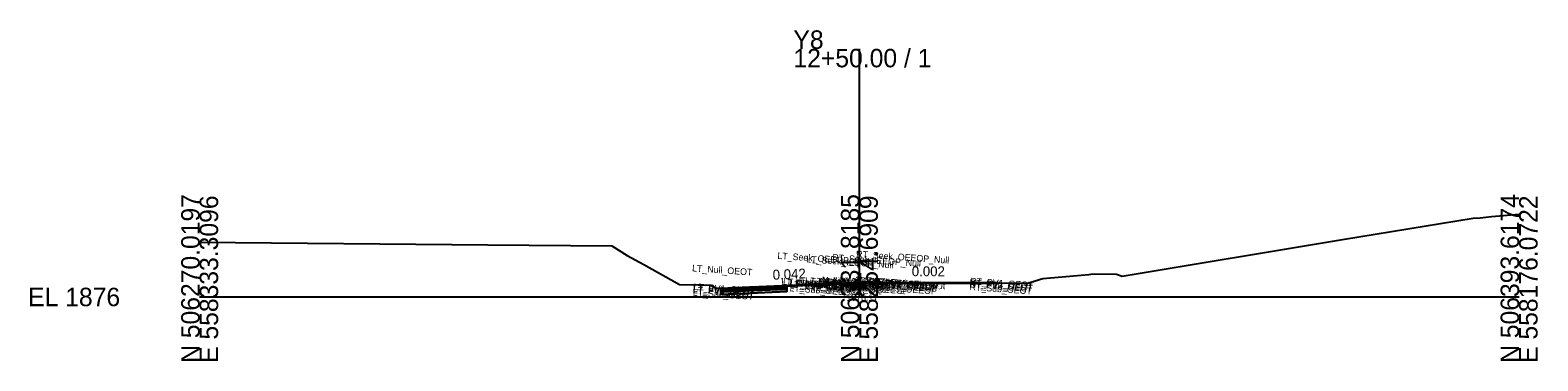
# Model space of a CAD drawing. Extents: x -26 to 203, y -10 to 8070.
# Drawn here: x -25.7 to 202.8, y 2490.3 to 2540.5 of the extents above; entities that cross this region are included whole.
import ezdxf

# ---------------------------------------------------------------- set-up
doc = ezdxf.new("R2010")
doc.units = 0
for name, color, linetype in [('Default', 7, 'Continuous'), ('Exist Cross Section Cell', 7, 'Continuous'), ('Exist XS Center Line Elevation Label', 7, 'Continuous'), ('Exist XS Ground Line', 7, 'Continuous'), ('Prop CMT Pvmt Course 1', 7, 'Continuous'), ('Prop CMT Pvmt Course 2', 7, 'Continuous'), ('Prop CMT Pvmt Course 3', 7, 'Continuous'), ('Prop CMT Pvmt Surface', 7, 'Continuous'), ('Prop CMT Subgrade Earthwork', 7, 'Continuous'), ('Prop XS Earthwork Shape', 7, 'Continuous'), ('Prop XS SE Text', 7, 'Continuous'), ('Typical Text Grade Point CELL', 7, 'Continuous')]:
    doc.layers.add(name, color=color, linetype=linetype)

msp = doc.modelspace()

# ---------------------------------------------------------------- linework, layer by layer
at = {"layer": 'Exist Cross Section Cell'}
for p, q in [((100, 2500), (100, 2537.64)), ((0, 2500), (100, 2500)), ((100, 2500), (200, 2500))]:
    msp.add_line(p, q, dxfattribs=at)
at = {"layer": 'Exist XS Ground Line'}
for p, q in [((173.25, 2508.73), (193.06, 2511.93)), ((193.06, 2511.93), (194.1, 2512)), ((194.1, 2512), (195.83, 2512.19)), ((195.83, 2512.19), (200, 2512.55)), ((0, 2508.32), (43.68, 2507.9)), ((43.68, 2507.9), (62.48, 2507.78)), ((62.48, 2507.78), (64.79, 2506.28)), ((139.81, 2503.16), (173.25, 2508.73)), ((64.79, 2506.28), (67.32, 2504.92)), ((67.32, 2504.92), (72.75, 2501.89)), ((125.34, 2502.02), (127.79, 2502.8)), ((127.79, 2502.8), (134.77, 2503.42)), ((134.77, 2503.42), (135.41, 2503.49)), ((135.41, 2503.49), (138.99, 2503.45)), ((138.99, 2503.45), (139.81, 2503.16)), ((72.75, 2501.89), (76.04, 2501.84)), ((76.04, 2501.84), (77.56, 2501.8)), ((77.56, 2501.8), (78.19, 2501.32)), ((78.19, 2501.32), (78.62, 2501.34)), ((78.62, 2501.34), (79.76, 2501.34)), ((79.76, 2501.34), (92.03, 2501.82)), ((92.03, 2501.82), (99.55, 2502.17)), ((99.55, 2502.17), (100, 2502.17)), ((100, 2502.17), (109.36, 2502.17)), ((109.36, 2502.17), (120.07, 2502.13)), ((120.07, 2502.13), (125, 2502.1)), ((125, 2502.1), (125.34, 2502.02))]:
    msp.add_line(p, q, dxfattribs=at)
at = {"layer": 'Prop CMT Pvmt Course 1'}
for points in [[(100, 2502.17), (98, 2502.1), (97.99, 2502.1), (94.01, 2501.93), (94, 2501.93), (79, 2501.28)], [(79, 2501.03), (89, 2501.45)], [(79, 2501.34), (79, 2501.03)], [(100, 2502.17), (102, 2502.16), (102.01, 2502.16), (105.99, 2502.15), (106, 2502.15), (121, 2502.13)]]:
    msp.add_lwpolyline(points, dxfattribs=at)
at = {"layer": 'Prop CMT Pvmt Course 2'}
for points in [[(89, 2501.45), (79, 2501.03)], [(79, 2500.78), (89, 2501.2)], [(79, 2501.03), (79, 2500.78)]]:
    msp.add_lwpolyline(points, dxfattribs=at)
at = {"layer": 'Prop CMT Pvmt Course 3'}
for points in [[(89, 2501.2), (79, 2500.78)], [(79, 2500.4), (89, 2500.82)], [(79, 2500.78), (79, 2500.4)]]:
    msp.add_lwpolyline(points, dxfattribs=at)
at = {"layer": 'Prop CMT Pvmt Surface'}
for points in [[(100, 2502.17), (98, 2502.1), (97.99, 2502.1), (94.01, 2501.93), (94, 2501.93), (79, 2501.28)], [(100, 2502.17), (102, 2502.16), (102.01, 2502.16), (105.99, 2502.15), (106, 2502.15), (121, 2502.13)]]:
    msp.add_lwpolyline(points, dxfattribs=at)
at = {"layer": 'Prop CMT Subgrade Earthwork'}
for points in [[(79, 2500.4), (79, 2501.34)], [(89, 2500.82), (79, 2500.4)], [(89, 2500.82), (89, 2501.7)]]:
    msp.add_lwpolyline(points, dxfattribs=at)
at = {"layer": 'Prop XS Earthwork Shape'}
for points in [[(105.99, 2502.15), (121, 2502.13), (121, 2502), (100, 2502.04), (89, 2501.57), (89, 2500.82), (79, 2500.4), (79, 2501.29), (84.39, 2501.52), (92.03, 2501.82), (98.15, 2502.11), (100, 2502.17), (102, 2502.16)], [(79, 2501.29), (79.76, 2501.34), (84.39, 2501.52)], [(98.15, 2502.11), (99.55, 2502.17), (100, 2502.17)], [(105.99, 2502.15), (121, 2502.13), (120.07, 2502.13), (109.36, 2502.17), (100, 2502.17), (102, 2502.16)]]:
    msp.add_lwpolyline(points, close=True, dxfattribs=at)

# ---------------------------------------------------------------- texts
at = {"layer": 'Default'}
msp.add_text('-', height=0.0001, dxfattribs=at).set_placement((0, 2500))
at = {"layer": 'Exist Cross Section Cell'}
for s, p in [('Y8', (90, 2537.64)), ('12+50.00 / 1', (90, 2534.84)), ('EL 1876', (-26, 2498.6))]:
    msp.add_text(s, height=2.8, dxfattribs=at).set_placement(p)
for s, p in [('N 506270.0197', (0, 2490)), ('E 558333.3096', (2.8, 2490)), ('N 506331.8185', (100, 2490)), ('E 558254.6909', (102.8, 2490)), ('N 506393.6174', (200, 2490)), ('E 558176.0722', (202.8, 2490))]:
    msp.add_text(s, height=2.8, rotation=90, dxfattribs=at).set_placement(p)
at = {"layer": 'Exist XS Center Line Elevation Label'}
msp.add_text('1878.17', height=1, dxfattribs=at).set_placement((98.03, 2499.42))
at = {"layer": 'Prop XS SE Text'}
for s, rotation, p in [('0.042', 2.4249, (86.89, 2502.61)), ('0.002', 359.8931, (107.94, 2503.15))]:
    msp.add_text(s, height=1.5, rotation=rotation, dxfattribs=at).set_placement(p)
at = {"layer": 'Typical Text Grade Point CELL'}
for s, p in [('RT_Seek_OEEOP_Null', (99.49, 2506.04)), ('LT_Null_OEOT', (74.62, 2503.89)), ('LT_Seek_OEEOP_Null', (87.55, 2505.78)), ('LT_Seek_IEEOP_Null', (91.93, 2505.26)), ('RT_Seek_IEEOP_Null', (95.87, 2505.51)), ('LT_PV_Sub_Tie_Out', (88.14, 2501.83)), ('LT_Null OEEOP Test', (88.4, 2501.87)), ('LT_PV2_OEEOP', (89.37, 2501.48)), ('LT_PV1_OEEOP', (89.49, 2501.6)), ('LT_Pvmt Out', (90.25, 2501.69)), ('LT_Null IEEOP Test', (91.78, 2501.98)), ('LT_PV_Sub_Tie_In', (92.76, 2501.97)), ('LT_PV2_IEEOP', (93.75, 2501.63)), ('LT_PV1_IEEOP', (93.87, 2501.74)), ('Null RT Pvmt Slope', (94.26, 2502.07)), ('Null LT Pvmt Slope', (94.32, 2502.08)), ('PV1_Overlay_Null', (94.75, 2501.91)), ('LT_Pvmt In', (94.84, 2501.82)), ('RT_PV_Sub_Tie_In', (96.7, 2502.03)), ('RT_Null IEEOP Test', (96.72, 2502.06)), ('PV2_PGL', (97.32, 2501.6)), ('PV1_PGL', (97.44, 2501.84)), ('RT_PV2_IEEOP', (97.69, 2501.71)), ('RT_PV3_IEEOP', (97.69, 2501.46)), ('RT_PV1_IEEOP', (97.81, 2501.83)), ('RT_Pvmt In', (98.8, 2501.88)), ('CL', (99.2, 2501.64)), ('RT_Null OEEOP Test', (99.34, 2502.08)), ('RT_PV_Sub_Tie_Out', (100.09, 2502.07)), ('RT_PV2_OEEOP', (101.31, 2501.73)), ('RT_PV3_OEEOP', (101.31, 2501.48)), ('RT_PV1_OEEOP', (101.43, 2501.85)), ('RT_Pvmt Out', (102.17, 2501.92)), ('RT_PV2_OEOT', (116.66, 2501.68)), ('RT_PV1_OEOT', (116.78, 2501.92)), ('LT_PV2_OEOT', (74.72, 2500.82)), ('LT_PV3_OEOT', (74.72, 2500.57)), ('LT_Sub_OEOT', (74.74, 2500.2)), ('LT_PV1_OEOT', (74.84, 2501.07)), ('LT_PV3_OEEOP', (89.37, 2501.23)), ('LT_Sub_OEEOP', (89.39, 2500.86)), ('LT_PV3_IEEOP', (93.75, 2501.38)), ('LT_Sub_IEEOP', (93.77, 2501)), ('Sub_PGL', (97.34, 2500.97)), ('PV3_PGL', (97.32, 2501.35)), ('RT_Sub_IEEOP', (97.71, 2501.08)), ('RT_Sub_OEEOP', (101.33, 2501.1)), ('RT_PV3_OEOT', (116.66, 2501.43)), ('RT_Sub_OEOT', (116.69, 2501.05))]:
    msp.add_text(s, height=1, rotation=356, dxfattribs=at).set_placement(p)

doc.saveas('drawing.dxf')
